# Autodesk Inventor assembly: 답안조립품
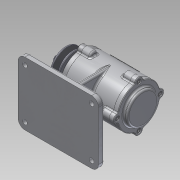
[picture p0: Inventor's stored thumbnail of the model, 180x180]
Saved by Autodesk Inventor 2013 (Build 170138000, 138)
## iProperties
Created: 2015-12
Part Number: 답안조립품
Document SubType Name: Assembly
Designer: Administrator
Author: Administrator
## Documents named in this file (11)
- C:\Users\Administrator\Desktop\451208V1018\답안조립품.iam
- C:\Users\Administrator\Desktop\451208V1018\본체.ipt
- C:\Users\Administrator\Desktop\451208V1018\커버.ipt
- C:\Users\Administrator\Desktop\451208V1018\커버2.ipt
- C:\Users\Administrator\Desktop\451208V1018\베어링 6204.ipt
- C:\Users\Administrator\Desktop\451208V1018\축.ipt
- C:\Users\Administrator\Desktop\451208V1018\키(4 x 4 x 12).ipt
- C:\Users\Administrator\Desktop\451208V1018\V-벨트풀리.ipt
- C:\Users\Administrator\Desktop\451208V1018\너트 M12x1.25.ipt
- C:\Users\Administrator\Desktop\451208V1018\오일실.ipt
- C:\Users\Administrator\Desktop\451208V1018\볼트 M4 x 12.ipt
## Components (6 placed, 5 different names)
1. KS B 2023 6204 - 20 x 47 x 14:1
2. KS B 2023 6204 - 20 x 47 x 14:2
3. KS B 1311 (I) 4 x 4 x 12:1
4. V-벨트풀리:1
5. KS B 1012 클래스 1 일반 - 미터 M12x1.25:1
6. KS B 2804 D D - 20 32 8:1
